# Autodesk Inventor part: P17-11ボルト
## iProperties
Shininess: 64.0
Length Units: 11269
Angle Units: 11279
Time Units: 11290
Mass Units: 11284
Length Display Precision: 2
Angle Display Precision: 1
Created: 2002-10
Part Number: P17-11ボルト
Document SubType Name: ﾓﾃﾞﾘﾝｸﾞ
Designer: 株式会社富士システム
Stock Number: P17-11ボルト
Density: 1 g/cm^3
Density: 0.0
Volumn: 0.0
Area: 0.0
PropertySet Name: Model Information
Control State: 0
Master: False
Checked Out: False
Author: 株式会社富士システム
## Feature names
1. 回転1 [Revolution]
2. 押し出し1 [Extrusion]
